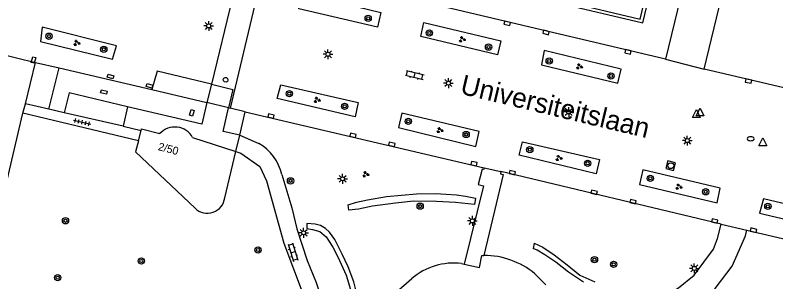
# Model space of a CAD drawing. Extents: x 131000 to 133014, y 396499 to 399001.
# Drawn here: x 131119.7 to 131216.5, y 397191 to 397225 of the extents above; entities that cross this region are included whole.
import ezdxf

# ---------------------------------------------------------------- set-up
doc = ezdxf.new("R2010")
doc.units = 0
for name, color, linetype in [('gg-anno-huisnummerreeks BGT', 7, 'Continuous'), ('gg-anno-openbare ruimte label', 7, 'Continuous'), ('gg-bbg-hoofdgebouw', 7, 'Continuous'), ('gg-bbg-luifel en loopbrug', 7, 'Continuous'), ('gg-bbg-overig bouwwerk', 7, 'Continuous'), ('gg-bbg-pand overbouw', 7, 'Continuous'), ('gg-bbg-pilaar overkapping', 7, 'Continuous'), ('gg-knt-BGT kruinlijn', 7, 'Continuous'), ('gg-knt-verharding', 7, 'Continuous'), ('gg-knt-verharding nz', 7, 'Continuous'), ('gt-grn-groengrens', 7, 'Continuous'), ('gt-grn-vlakafsluiter', 7, 'Continuous'), ('gt-grn-weggrens', 7, 'Continuous'), ('gt-symb-boom', 7, 'Continuous'), ('gt-symb-brandkraan', 7, 'Continuous'), ('gt-symb-groenvak', 7, 'Continuous'), ('gt-symb-klinker verharding', 7, 'Continuous'), ('gt-symb-kolk', 7, 'Continuous'), ('gt-symb-kolk center center', 7, 'Continuous'), ('gt-symb-lichtmast', 7, 'Continuous'), ('gt-symb-rioolschacht', 7, 'Continuous'), ('gt-symb-tegel verharding', 7, 'Continuous'), ('gt-symb-waterafsluiter', 7, 'Continuous')]:
    doc.layers.add(name, color=color, linetype=linetype)

# ---------------------------------------------------------------- blocks, each defined once
blk = doc.blocks.new('gt0-KOLKCC')
at = {"layer": 'gt-symb-kolk center center'}
blk.add_lwpolyline([(-0.375, 0.2), (0.375, 0.2), (0.375, -0.2), (-0.375, -0.2)], close=True, dxfattribs=at)
blk = doc.blocks.new('gt0-BOOM')
at = {"layer": 'gt-symb-boom'}
for radius in [0.4, 0.2]:
    blk.add_circle((0, 0), radius, dxfattribs=at)
blk = doc.blocks.new('gt0-GRVAK')
at = {"layer": 'gt-symb-groenvak'}
for p, q in [((-0.11, 0.189), (-0.228, 0.24)), ((-0.182, 0.153), (0.088, 0.153)), ((-0.091, 0.211), (-0.156, 0.322)), ((-0.047, 0.214), (-0.047, 0.393)), ((-0.004, 0.211), (0.061, 0.322)), ((0.015, 0.189), (0.133, 0.24)), ((0.262, -0.052), (0.197, 0.059)), ((0.305, -0.049), (0.305, 0.13)), ((0.349, -0.052), (0.414, 0.059)), ((-0.245, -0.228), (-0.363, -0.177)), ((-0.318, -0.264), (-0.047, -0.264)), ((-0.226, -0.206), (-0.291, -0.095)), ((-0.183, -0.203), (-0.183, -0.024)), ((-0.139, -0.206), (-0.074, -0.095)), ((-0.12, -0.228), (-0.002, -0.177)), ((0.243, -0.074), (0.125, -0.023)), ((0.17, -0.11), (0.441, -0.11)), ((0.368, -0.074), (0.486, -0.023))]:
    blk.add_line(p, q, dxfattribs=at)
blk = doc.blocks.new('gt0-WAFSL')
at = {"layer": 'gt-symb-waterafsluiter'}
for p, q in [((-0.5, -0.333), (0, 0.667)), ((0, 0.667), (0.5, -0.333)), ((0.5, -0.333), (-0.5, -0.333))]:
    blk.add_line(p, q, dxfattribs=at)
blk = doc.blocks.new('gt0-KOLK')
at = {"layer": 'gt-symb-kolk'}
blk.add_lwpolyline([(0, 0), (0.375, 0), (0.375, 0.4), (-0.375, 0.4), (-0.375, 0), (0, 0)], dxfattribs=at)
blk = doc.blocks.new('gt0-BR')
at = {"layer": 'gt-symb-brandkraan'}
for centre, radius, start, end in [((-0.244, 0), 0.206, 107.56694, 252.43307), ((0.599, -2.664), 3, 106.89205, 107.56694), ((0, -0.691), 0.938, 73.10799, 106.89205), ((-0.599, -2.664), 3, 72.43309, 73.10799), ((0.244, 0), 0.206, 287.56695, 72.43309), ((0.599, 2.664), 3, 252.43307, 253.10797), ((0, 0.691), 0.938, 253.10797, 286.89206), ((-0.599, 2.664), 3, 286.89206, 287.56695)]:
    blk.add_arc(centre, radius, start, end, dxfattribs=at)
blk = doc.blocks.new('gt0-LMAST')
at = {"layer": 'gt-symb-lichtmast'}
for p, q in [((-0.182, 0.173), (-0.447, 0.438)), ((-0.005, 0.246), (-0.005, 0.621)), ((0.172, 0.173), (0.437, 0.438)), ((-0.255, -0.004), (-0.63, -0.004)), ((-0.182, -0.181), (-0.447, -0.446)), ((-0.005, -0.254), (-0.005, -0.629)), ((0.437, -0.446), (0.172, -0.181)), ((0.245, -0.004), (0.62, -0.004))]:
    blk.add_line(p, q, dxfattribs=at)
blk.add_circle((-0.005, -0.004), 0.25, dxfattribs=at)
blk = doc.blocks.new('gt0-RS')
at = {"layer": 'gt-symb-rioolschacht'}
blk.add_lwpolyline([(-0.5, -0.5), (0.5, -0.5), (0.5, 0.5), (-0.5, 0.5)], close=True, dxfattribs=at)
blk.add_circle((0, 0), 0.375, dxfattribs=at)
blk = doc.blocks.new('gt0-KL1')
at = {"layer": 'gt-symb-klinker verharding'}
for p, q in [((-1.15, 0.3), (1.15, 0.3)), ((-1, -0.3), (-1, 0.3)), ((-0.5, 0.3), (-0.5, 0.45)), ((0, -0.3), (0, 0.3)), ((0.5, 0.3), (0.5, 0.45)), ((1, -0.3), (1, 0.3)), ((-1.15, -0.3), (1.15, -0.3)), ((-0.5, -0.45), (-0.5, -0.3)), ((0.5, -0.45), (0.5, -0.3))]:
    blk.add_line(p, q, dxfattribs=at)
blk = doc.blocks.new('gt0-TEG1')
at = {"layer": 'gt-symb-tegel verharding'}
for p, q in [((-1.125, 0), (1.125, 0)), ((-0.9, -0.25), (-0.9, 0.25)), ((-0.45, -0.25), (-0.45, 0.25)), ((0, -0.25), (0, 0.25)), ((0.45, -0.25), (0.45, 0.25)), ((0.9, -0.25), (0.9, 0.25))]:
    blk.add_line(p, q, dxfattribs=at)

msp = doc.modelspace()

# ---------------------------------------------------------------- linework, layer by layer
at = {"layer": 'gg-bbg-hoofdgebouw'}
for p, q in [((131135.395, 397208.969), (131135.745, 397210.299)), ((131142.29, 397209.4), (131147.8, 397207.62)), ((131146.37, 397201.73), (131147.8, 397207.62)), ((131176.5, 397193.36), (131176.848, 397193.282)), ((131185.82, 397192.05), (131187.24, 397190.63))]:
    msp.add_line(p, q, dxfattribs=at)
for points in [[(131135.745, 397210.299), (131135.8, 397210.51), (131138.13, 397209.9)], [(131135.395, 397208.969), (131135.03, 397207.58), (131142.6, 397200.42)], [(131176.848, 397193.282), (131178.77, 397192.85), (131179.08, 397194.37), (131179.344, 397194.375)], [(131168.22, 397187.86), (131169.13, 397188.65), (131168.2, 397189.72), (131170.19, 397191.44)]]:
    msp.add_lwpolyline(points, dxfattribs=at)
for centre, radius, start, end in [((131140.031, 397208.163), 2.575, 28.69966, 137.59307), ((131144.171, 397201.98), 2.214, 224.80845, 353.51419), ((131179.398, 397184.344), 10.031, 50.1926, 90.3093), ((131175.536, 397185.201), 8.216, 83.25951, 130.58829)]:
    msp.add_arc(centre, radius, start, end, dxfattribs=at)
at = {"layer": 'gg-bbg-luifel en loopbrug'}
for p, q in [((131151.441, 397231.458), (131147.058, 397213.155)), ((131147.51, 397227.921), (131144.679, 397216.19)), ((131144.679, 397216.19), (131144.116, 397213.86)), ((131134.02, 397213.31), (131133.46, 397210.84)), ((131146.87, 397213.2), (131147.058, 397213.155)), ((131133.46, 397210.84), (131135.745, 397210.299)), ((131147.8, 397207.62), (131148.29, 397209.69))]:
    msp.add_line(p, q, dxfattribs=at)
for points in [[(131144.116, 397213.86), (131143.45, 397211.1), (131134.02, 397213.31)], [(131148.29, 397209.69), (131146.18, 397210.16), (131146.87, 397213.2)]]:
    msp.add_lwpolyline(points, dxfattribs=at)
at = {"layer": 'gg-bbg-overig bouwwerk'}
for p, q in [((131148.99, 397212.69), (131147.058, 397213.155)), ((131148.29, 397209.69), (131148.99, 397212.69))]:
    msp.add_line(p, q, dxfattribs=at)
at = {"layer": 'gg-bbg-pand overbouw'}
msp.add_lwpolyline([(131153.36, 397235.402), (131199.24, 397224.48), (131201.468, 397233.879)], dxfattribs=at)
at = {"layer": 'gg-bbg-pilaar overkapping'}
msp.add_lwpolyline([(131146.741, 397216.905), (131146.782, 397216.724), (131146.708, 397216.554), (131146.548, 397216.46), (131146.364, 397216.478), (131146.225, 397216.601), (131146.184, 397216.782), (131146.258, 397216.952), (131146.418, 397217.046), (131146.602, 397217.028), (131146.741, 397216.905)], dxfattribs=at)
at = {"layer": 'gg-knt-BGT kruinlijn'}
msp.add_lwpolyline([(131152.029, 397232.921), (131158.186, 397231.458), (131158.703, 397233.697), (131199.582, 397224.003), (131201.905, 397233.778)], dxfattribs=at)
at = {"layer": 'gg-knt-verharding'}
for p, q in [((131207.382, 397218.117), (131218.178, 397263.439)), ((131205.679, 397232.905), (131202.46, 397219.38)), ((131202.46, 397219.38), (131151.441, 397231.458)), ((131121.03, 397213.69), (131122.28, 397218.97)), ((131122.28, 397218.97), (131125.318, 397218.264)), ((131123.991, 397213.01), (131125.318, 397218.264)), ((131125.318, 397218.264), (131137.118, 397215.528)), ((131240.602, 397210.248), (131207.382, 397218.117)), ((131137.118, 397215.528), (131144.116, 397213.86)), ((131120.71, 397212.48), (131121.03, 397213.69)), ((131123.991, 397213.01), (131121.03, 397213.69)), ((131125.943, 397212.562), (131123.991, 397213.01)), ((131115.86, 397191.99), (131120.71, 397212.48)), ((131135.395, 397208.969), (131120.71, 397212.48)), ((131133.46, 397210.84), (131125.943, 397212.562)), ((131148.99, 397212.69), (131179.381, 397205.557)), ((131148.29, 397209.69), (131150.71, 397208.63)), ((131209.53, 397198.36), (131181.491, 397205.053)), ((131212.81, 397197.59), (131238.936, 397191.414))]:
    msp.add_line(p, q, dxfattribs=at)
for points in [[(131155.802, 397225.788), (131156.282, 397227.795), (131166.249, 397225.33), (131165.796, 397223.446), (131155.802, 397225.788)], [(131123.133, 397223.446), (131122.918, 397221.624), (131132.086, 397219.378), (131132.598, 397221.082), (131123.133, 397223.446)], [(131181.494, 397221.693), (131181.06, 397219.935), (131171.31, 397222.254), (131171.708, 397224.029), (131181.494, 397221.693)], [(131187.001, 397220.467), (131186.67, 397218.645), (131196.38, 397216.339), (131196.795, 397218.093), (131187.001, 397220.467)], [(131144.679, 397216.19), (131137.77, 397217.86), (131137.118, 397215.528)], [(131153.047, 397214.349), (131153.523, 397216.098), (131163.327, 397213.847), (131162.946, 397212.039), (131153.047, 397214.349)], [(131134.02, 397213.31), (131126.58, 397215.11), (131125.943, 397212.562)], [(131178.323, 397208.261), (131178.736, 397210.16), (131168.902, 397212.484), (131168.473, 397210.676), (131178.323, 397208.261)], [(131183.818, 397207.151), (131184.235, 397208.851), (131194.057, 397206.601), (131193.612, 397204.783), (131183.818, 397207.151)], [(131147.8, 397207.62), (131148.41, 397207.4), (131150.84, 397205.71), (131151.7, 397203.9), (131153.88, 397195.95), (131156.24, 397189.73), (131157.29, 397186.38), (131157.38, 397185.78), (131157.33, 397184.35), (131157.04, 397182.57), (131156.45, 397180.71), (131155.84, 397179.55), (131154.56, 397177.81), (131152.72, 397175.9), (131152.24, 397175.25), (131148.243, 397160.282)], [(131179.381, 397205.557), (131179.327, 397205.332), (131179.103, 397205.385), (131178.634, 397203.4), (131179.295, 397203.243), (131176.848, 397193.282)], [(131181.491, 397205.053), (131181.454, 397204.773), (131181.799, 397204.707), (131179.344, 397194.375)], [(131199.558, 397205.306), (131199.154, 397203.425), (131209.006, 397201.079), (131209.406, 397202.954), (131199.558, 397205.306)], [(131153.62, 397204.68), (131154.93, 397200.45), (131155.54, 397197.79), (131156.88, 397193.74), (131158.01, 397190.93), (131158.87, 397188.39), (131159.68, 397185.58), (131160.4, 397182.12), (131161.14, 397180.61), (131161.91, 397179.42), (131163.09, 397178.03), (131164.44, 397176.89), (131166.09, 397176.17), (131170.02, 397174.75), (131173.17, 397174.01), (131175.01, 397173.79), (131176.9, 397174), (131178.17, 397174.71), (131184.08, 397178.43), (131188.34, 397181.67)], [(131214.893, 397201.613), (131214.414, 397199.755), (131224.319, 397197.426), (131224.785, 397199.263), (131214.893, 397201.613)], [(131196.78, 397186.43), (131199.38, 397187.49), (131204.08, 397190.26), (131206.09, 397191.88), (131208.53, 397195.18), (131209.07, 397196.53), (131209.53, 397198.36)], [(131203.384, 397172.31), (131202.05, 397177.54), (131202.1, 397180.65), (131202.27, 397181.67), (131203.51, 397184.78), (131204.96, 397186.93), (131205.61, 397187.55), (131207.21, 397188.73), (131208.78, 397190.18), (131210.91, 397193.02), (131212.63, 397196.88), (131212.81, 397197.59)]]:
    msp.add_lwpolyline(points, dxfattribs=at)
msp.add_arc((131147.87, 397203.491), 5.871, 11.68334, 61.07546, dxfattribs=at)
at = {"layer": 'gg-knt-verharding nz'}
msp.add_line((131146.87, 397213.2), (131144.116, 397213.86), dxfattribs=at)
msp.add_lwpolyline([(131144.679, 397216.19), (131147.41, 397215.53), (131146.87, 397213.2)], dxfattribs=at)
at = {"layer": 'gt-grn-groengrens'}
msp.add_line((131185.75, 397195.928), (131185.617, 397195.282), dxfattribs=at)
for points in [[(131178.276, 397201.681), (131178.133, 397200.862), (131175.726, 397201.138), (131173.309, 397201.261), (131170.404, 397201.296), (131168.117, 397201.034), (131165.188, 397200.656), (131163.405, 397200.283), (131162.153, 397200.149), (131162.078, 397200.845), (131163.124, 397201.167), (131164.517, 397201.448), (131166.972, 397201.877), (131168.845, 397202.076), (131170.75, 397202.216), (131173.193, 397202.288), (131174.522, 397202.205), (131175.865, 397202.121), (131177.006, 397201.934), (131178.276, 397201.681)], [(131168.024, 397178.519), (131168.266, 397179.277), (131167.508, 397179.519), (131166.649, 397179.959), (131165.321, 397180.901), (131164.583, 397181.773), (131164.121, 397182.956), (131163.886, 397184.28), (131163.701, 397186.053), (131163.591, 397187.113), (131163.413, 397188.442), (131163.197, 397189.512), (131162.776, 397191.007), (131162.09, 397192.947), (131161.306, 397194.539), (131160.385, 397196.408), (131159.695, 397197.343), (131159.174, 397197.8), (131158.577, 397198.181), (131157.863, 397198.38), (131156.821, 397198.444)], [(131156.821, 397198.444), (131156.821, 397197.794), (131157.518, 397197.689), (131158.489, 397197.42), (131159.297, 397196.752), (131160.122, 397195.447), (131160.754, 397194.217), (131161.819, 397191.853), (131162.374, 397190.034), (131162.835, 397188.164), (131162.999, 397186.897), (131163.061, 397185.373), (131163.215, 397184.098), (131163.37, 397183.282), (131163.663, 397182.296), (131163.902, 397181.712), (131164.341, 397180.872), (131164.983, 397180.082), (131166.136, 397179.327), (131167.265, 397178.753), (131168.024, 397178.519)], [(131192.029, 397190.967), (131190.103, 397192.257), (131188.475, 397193.509), (131187.106, 397194.48), (131186.122, 397195.066), (131185.617, 397195.282)], [(131185.75, 397195.928), (131186.856, 397195.436), (131188.3, 397194.453), (131189.929, 397193.172), (131191.557, 397191.892), (131193.462, 397191.011)]]:
    msp.add_lwpolyline(points, dxfattribs=at)
at = {"layer": 'gt-grn-vlakafsluiter'}
msp.add_line((131179.381, 397205.557), (131181.491, 397205.053), dxfattribs=at)
at = {"layer": 'gt-grn-weggrens'}
for p, q in [((131099.32, 397224.51), (131122.28, 397218.97)), ((131202.46, 397219.38), (131207.382, 397218.117)), ((131209.53, 397198.36), (131212.81, 397197.59))]:
    msp.add_line(p, q, dxfattribs=at)

# ---------------------------------------------------------------- block references
at = {"layer": 'gt-symb-boom'}
for p in [(131164.62, 397224.571), (131124.007, 397222.303), (131172.413, 397222.722), (131130.988, 397220.643), (131179.932, 397220.913), (131187.652, 397219.144), (131195.505, 397217.228), (131154.603, 397214.975), (131161.622, 397213.366), (131169.723, 397211.454), (131177.087, 397209.783), (131185.18, 397207.863), (131192.548, 397206.126), (131154.747, 397203.88), (131200.506, 397204.191), (131207.565, 397202.489), (131171.234, 397200.659), (131215.468, 397200.63), (131126.117, 397198.798), (131150.614, 397195.067), (131135.772, 397193.671), (131193.407, 397193.845), (131195.845, 397193.26), (131125.127, 397191.554)]:
    msp.add_blockref('gt0-BOOM', p, dxfattribs=at)
at = {"layer": 'gt-symb-brandkraan'}
msp.add_blockref('gt0-BR', (131213.286, 397209.244), dxfattribs=at)
at = {"layer": 'gt-symb-groenvak'}
for p in [(131127.541, 397221.433), (131176.577, 397221.9), (131191.475, 397218.439), (131158.104, 397214.184), (131173.724, 397210.326), (131188.87, 397206.777), (131164.287, 397204.721), (131204.124, 397203.122)]:
    msp.add_blockref('gt0-GRVAK', p, dxfattribs=at)
at = {"layer": 'gt-symb-klinker verharding'}
for p, rotation in [((131170.549, 397217.36), -13.174926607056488), ((131155.052, 397194.807), -72.72457972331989)]:
    msp.add_blockref('gt0-KL1', p, dxfattribs=dict(at, rotation=rotation))
at = {"layer": 'gt-symb-kolk'}
for p, rotation in [((131182.351, 397224.134), 166.5889281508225), ((131187.295, 397222.978), 164.62927456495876), ((131197.72, 397220.508), 166.75619797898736), ((131213.049, 397216.783), 168.2854747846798), ((131152.212, 397211.933), -12.646853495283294), ((131162.639, 397209.487), -12.646853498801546), ((131167.587, 397208.33), -12.47907180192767), ((131178.041, 397205.887), -12.242859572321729), ((131182.921, 397204.724), -14.119602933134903), ((131193.321, 397202.235), -13.411071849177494), ((131198.267, 397201.051), -13.35534096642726), ((131208.648, 397198.569), -14.064036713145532), ((131213.593, 397197.404), -13.24380202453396)]:
    msp.add_blockref('gt0-KOLK', p, dxfattribs=dict(at, rotation=rotation))
at = {"layer": 'gt-symb-kolk center center'}
for p, rotation in [((131122.032, 397219.272), 73.37760386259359), ((131131.834, 397217.18), -15.064233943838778), ((131136.805, 397215.986), -14.244742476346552), ((131131, 397215.195), -13.71646932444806), ((131142.201, 397212.546), -106.2051853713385)]:
    msp.add_blockref('gt0-KOLKCC', p, dxfattribs=dict(at, rotation=rotation))
at = {"layer": 'gt-symb-lichtmast'}
for p in [(131144.335, 397223.614), (131159.509, 397220.003), (131174.832, 397216.331), (131190.144, 397212.656), (131205.226, 397209.012), (131161.367, 397204.142), (131177.883, 397198.79), (131156.408, 397197.267), (131206.117, 397192.741)]:
    msp.add_blockref('gt0-LMAST', p, dxfattribs=at)
at = {"layer": 'gt-symb-rioolschacht', "rotation": -14.18918015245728}
msp.add_blockref('gt0-RS', (131203.115, 397205.809), dxfattribs=at)
at = {"layer": 'gt-symb-tegel verharding', "rotation": -13.411071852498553}
msp.add_blockref('gt0-TEG1', (131128.238, 397211.361), dxfattribs=at)
at = {"layer": 'gt-symb-waterafsluiter'}
for p in [(131206.372, 397212.296), (131206.842, 397212.481), (131214.819, 397208.679)]:
    msp.add_blockref('gt0-WAFSL', p, dxfattribs=at)

# ---------------------------------------------------------------- texts
at = {"layer": 'gg-anno-huisnummerreeks BGT'}
msp.add_text('2/50', height=1, rotation=345.3, dxfattribs=at).set_placement((131137.821, 397207.812))
at = {"layer": 'gg-anno-openbare ruimte label'}
msp.add_text('Universiteitslaan', height=2.5, rotation=346.6, dxfattribs=at).set_placement((131176.212, 397214.999))

doc.saveas('drawing.dxf')
